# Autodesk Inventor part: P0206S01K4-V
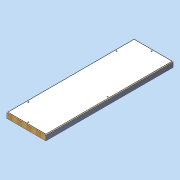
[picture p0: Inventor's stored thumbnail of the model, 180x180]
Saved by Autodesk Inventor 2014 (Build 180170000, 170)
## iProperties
Created: 2011-04
Part Number: P0206S01K4-V
Document SubType Name: Modeling
Designer: david.appleford
Density: 0.224144 g/cm^3
Description: 0.5w x 1.5w 01 Panel - 5 Locks
Mass: 17000 g
Surface Area: 22794 cm^2
Volume: 75844.2 cm^3
Cost Center: £69.00
Material: Generic
Appearance: Wood (Pine)
Justset: False
Title: 0.5w x 1.5w 01 Panel - 5 Locks
Author: david.appleford
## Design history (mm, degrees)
sketch "Sketch1"
  geometry: L1 (0, 0)-(610, 0); L2 (610, 0)-(610, 1830); L3 (610, 1830)-(0, 1830); L4 (0, 1830)-(0, 0); L5 (34, 1796)-(576, 1796); L6 (576, 1796)-(576, 34); L7 (576, 34)-(34, 34); L8 (34, 34)-(34, 1796)
  constraints: 16 end point, 4 parallel, 2 perpendicular, 1 horizontal, 3 other
  dimensions: "d0" = 610 distance between parallel lines of L2 L4 (= 0.5 x w); "d1" = 1830 distance between parallel lines of L1 L3 (= 1.5 x w); "d2" = 34 distance between parallel lines of L5 L3 (= 0.5 x t)
extrude "Extrusion1" new body sketch "Sketch1" distance "d3" = 68 (= t); taper "d4" = 0 deg
sketch "Sketch2"
  geometry: L1 (576, 1796)-(576, 34) reference; L2 (34, 1796)-(576, 1796) reference; L3 (34, 34)-(34, 1796) reference; L4 (576, 34)-(34, 34) reference; L5 (566, 1786)-(566, 44); L6 (566, 44)-(44, 44); L7 (44, 44)-(44, 1786); L8 (44, 1786)-(566, 1786); 1 further point
  constraints: 8 end point, 3 other
  dimensions: "d5" = 10 distance between parallel lines of L8 L2
extrude "Extrusion2" join sketch "Sketch2" distance "d6" = 6 (= sw); taper "d7" = 0 deg
sketch "Sketch3"
  geometry: L1 (-44, 1786)-(-566, 1786) reference; L2 (-566, 1786)-(-566, 44) reference; L3 (-44, 44)-(-44, 1786) reference; L4 (-566, 44)-(-44, 44) reference; 1 further point
extrude "Extrusion3" join sketch "Sketch3" distance "d8" = 6 (= sw); taper "d9" = 0 deg
sketch "Sketch4"
  geometry: L1 (34, 1796)-(576, 1796) reference; L2 (576, 1796)-(576, 34) reference; L3 (576, 34)-(34, 34) reference; L4 (34, 34)-(34, 1796) reference; 6 further points
  constraints: 1 vertical alignment
  dimensions: "d13" = 28 distance from line of point (62, 305) L4 (= k); "d16" = 305 vertical distance of point (62, 305) point (0, 0) (= 0.25 x w); "d17" = 1220 distance of point (62, 305) point (62, 1525) (= w); "d19" = 610 vertical distance of point (548, 915) point (62, 305) (= 0.5 x w); "d29" = 28 distance from line of point (305, 62) L3; "d30" = 271 distance from line of point (305, 62) L4; "d31" = 28 distance from line of L1 point (305, 1768) (= d29)
hole "Hole1" sketch "Sketch4" at (62, 1525), (62, 305), (548, 915), (305, 62), (305, 1768) diameter "d22" = 16.3; stored, may be unused: countersink angle "d26" = 90 deg, drill point angle "d28" = 118 deg; dims "d23" = 6, "d24" = 4, "d25" = 2, "d27" = 6
body "Solid1"
node "Projected Loop1"
other parameters: "w" = 1220 [user parameter; used in 5 equation terms], "t" = 68 [user parameter; used in 2 equation terms], "e" = 16 [user parameter], "sw" = 6 [user parameter; used in 2 equation terms], "sc" = 9 [user parameter], "sf" = 12 [user parameter], "k" = 28 [user parameter; used in 1 equation term], "hd" = 12 [user parameter]
